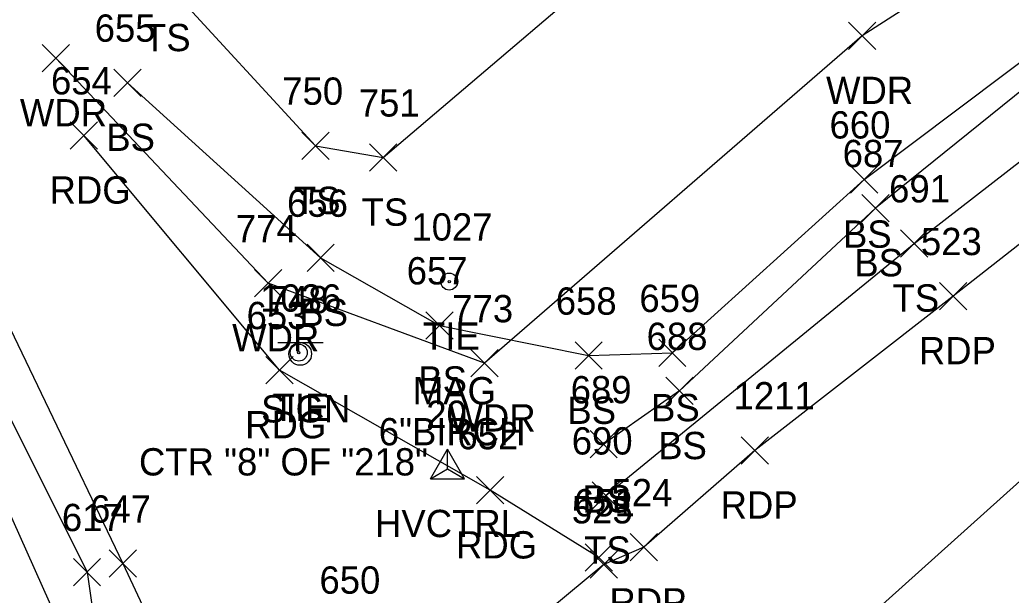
# Model space of a CAD drawing. Extents: x 1528286 to 1556263, y 492387 to 508952.
# Drawn here: x 1528468.6 to 1528541.2, y 492695.5 to 492737.7 of the extents above; entities that cross this region are included whole.
import ezdxf

# ---------------------------------------------------------------- set-up
doc = ezdxf.new("R2010")
doc.units = 0
for name, color, linetype in [('C_A', 7, 'Continuous'), ('C_C', 7, 'Continuous'), ('C_I', 7, 'Continuous'), ('CBP', 7, 'Continuous'), ('CPSM', 7, 'Continuous'), ('L_A', 7, 'Continuous'), ('L_I', 7, 'Continuous'), ('L_TIC', 7, 'Continuous'), ('LAWA', 7, 'Continuous'), ('LELB', 7, 'Continuous'), ('P_A', 7, 'Continuous'), ('P_I', 7, 'Continuous'), ('P_TIC', 7, 'Continuous'), ('PET', 7, 'Continuous'), ('PEU', 7, 'Continuous'), ('PRC', 7, 'Continuous'), ('S_A', 7, 'Continuous'), ('S_I', 7, 'Continuous'), ('SSGN', 7, 'Continuous')]:
    doc.layers.add(name, color=color, linetype=linetype)

msp = doc.modelspace()

# ---------------------------------------------------------------- linework, layer by layer
at = {"layer": 'CBP'}
for centre, radius in [((1528500.051, 492718.519), 0.625), ((1528500.051, 492718.519), 0.625), ((1528500.051, 492718.519), 0.0833), ((1528500.051, 492718.519), 0.0833), ((1528489.024, 492713.312), 0.625), ((1528489.024, 492713.312), 0.625), ((1528489.024, 492713.312), 0.0833), ((1528489.024, 492713.312), 0.0833)]:
    msp.add_circle(centre, radius, dxfattribs=at)
at = {"layer": 'CPSM'}
for p, q in [((1528498.671, 492704.074), (1528499.921, 492706.239)), ((1528498.671, 492704.074), (1528499.921, 492706.239)), ((1528501.171, 492704.074), (1528499.921, 492706.239)), ((1528499.921, 492704.795), (1528499.921, 492706.239)), ((1528501.171, 492704.074), (1528499.921, 492706.239)), ((1528499.921, 492704.795), (1528499.921, 492706.239)), ((1528498.671, 492704.074), (1528499.921, 492704.795)), ((1528498.671, 492704.074), (1528499.921, 492704.795)), ((1528499.921, 492704.795), (1528499.921, 492704.795)), ((1528499.921, 492704.795), (1528501.171, 492704.074)), ((1528499.921, 492704.795), (1528499.921, 492704.795)), ((1528499.921, 492704.795), (1528501.171, 492704.074)), ((1528498.671, 492704.074), (1528501.171, 492704.074)), ((1528498.671, 492704.074), (1528501.171, 492704.074))]:
    msp.add_line(p, q, dxfattribs=at)
at = {"layer": 'L_TIC'}
for points in [[(1528529.313, 492735.522), (1528531.313, 492737.522)], [(1528531.313, 492735.522), (1528529.313, 492737.522)], [(1528529.313, 492735.522), (1528531.313, 492737.522)], [(1528531.313, 492735.522), (1528529.313, 492737.522)], [(1528470.218, 492733.886), (1528472.218, 492735.886)], [(1528472.218, 492733.886), (1528470.218, 492735.886)], [(1528470.218, 492733.886), (1528472.218, 492735.886)], [(1528472.218, 492733.886), (1528470.218, 492735.886)], [(1528475.47, 492732.086), (1528477.47, 492734.086)], [(1528477.47, 492732.086), (1528475.47, 492734.086)], [(1528475.47, 492732.086), (1528477.47, 492734.086)], [(1528477.47, 492732.086), (1528475.47, 492734.086)], [(1528489.259, 492727.467), (1528491.259, 492729.467)], [(1528491.259, 492727.467), (1528489.259, 492729.467)], [(1528489.259, 492727.467), (1528491.259, 492729.467)], [(1528491.259, 492727.467), (1528489.259, 492729.467)], [(1528494.219, 492726.605), (1528496.219, 492728.605)], [(1528496.219, 492726.605), (1528494.219, 492728.605)], [(1528494.219, 492726.605), (1528496.219, 492728.605)], [(1528496.219, 492726.605), (1528494.219, 492728.605)], [(1528529.473, 492724.995), (1528531.473, 492726.995)], [(1528531.473, 492724.995), (1528529.473, 492726.995)], [(1528529.473, 492724.995), (1528531.473, 492726.995)], [(1528531.473, 492724.995), (1528529.473, 492726.995)], [(1528530.303, 492722.898), (1528532.303, 492724.898)], [(1528532.303, 492722.898), (1528530.303, 492724.898)], [(1528530.303, 492722.898), (1528532.303, 492724.898)], [(1528532.303, 492722.898), (1528530.303, 492724.898)], [(1528533.14, 492720.314), (1528535.14, 492722.314)], [(1528535.14, 492720.314), (1528533.14, 492722.314)], [(1528533.14, 492720.314), (1528535.14, 492722.314)], [(1528535.14, 492720.314), (1528533.14, 492722.314)], [(1528489.627, 492719.26), (1528491.627, 492721.26)], [(1528491.627, 492719.26), (1528489.627, 492721.26)], [(1528489.627, 492719.26), (1528491.627, 492721.26)], [(1528491.627, 492719.26), (1528489.627, 492721.26)], [(1528485.776, 492717.401), (1528487.776, 492719.401)], [(1528487.776, 492717.401), (1528485.776, 492719.401)], [(1528485.776, 492717.401), (1528487.776, 492719.401)], [(1528487.776, 492717.401), (1528485.776, 492719.401)], [(1528498.344, 492714.307), (1528500.344, 492716.307)], [(1528500.344, 492714.307), (1528498.344, 492716.307)], [(1528498.344, 492714.307), (1528500.344, 492716.307)], [(1528500.344, 492714.307), (1528498.344, 492716.307)], [(1528509.272, 492712.09), (1528511.272, 492714.09)], [(1528511.272, 492712.09), (1528509.272, 492714.09)], [(1528509.272, 492712.09), (1528511.272, 492714.09)], [(1528511.272, 492712.09), (1528509.272, 492714.09)], [(1528515.407, 492712.286), (1528517.407, 492714.286)], [(1528517.407, 492712.286), (1528515.407, 492714.286)], [(1528515.407, 492712.286), (1528517.407, 492714.286)], [(1528517.407, 492712.286), (1528515.407, 492714.286)], [(1528501.638, 492711.533), (1528503.638, 492713.533)], [(1528503.638, 492711.533), (1528501.638, 492713.533)], [(1528501.638, 492711.533), (1528503.638, 492713.533)], [(1528503.638, 492711.533), (1528501.638, 492713.533)], [(1528515.93, 492709.506), (1528517.93, 492711.506)], [(1528517.93, 492709.506), (1528515.93, 492711.506)], [(1528515.93, 492709.506), (1528517.93, 492711.506)], [(1528517.93, 492709.506), (1528515.93, 492711.506)], [(1528510.372, 492705.597), (1528512.372, 492707.597)], [(1528512.372, 492705.597), (1528510.372, 492707.597)], [(1528510.372, 492705.597), (1528512.372, 492707.597)], [(1528512.372, 492705.597), (1528510.372, 492707.597)], [(1528510.531, 492701.846), (1528512.531, 492703.846)], [(1528512.531, 492701.846), (1528510.531, 492703.846)], [(1528510.531, 492701.846), (1528512.531, 492703.846)], [(1528512.531, 492701.846), (1528510.531, 492703.846)], [(1528472.5, 492696.234), (1528474.5, 492698.234)], [(1528474.5, 492696.234), (1528472.5, 492698.234)], [(1528472.5, 492696.234), (1528474.5, 492698.234)], [(1528474.5, 492696.234), (1528472.5, 492698.234)]]:
    msp.add_lwpolyline(points, dxfattribs=at)
at = {"layer": 'LAWA'}
for points in [[(1528662.937, 492830.692), (1528634.182, 492809.012), (1528604.188, 492788.279), (1528566.961, 492760.007), (1528530.313, 492736.522), (1528502.638, 492712.533), (1528486.776, 492718.401), (1528471.218, 492734.886)], [(1528662.937, 492830.692), (1528634.182, 492809.012), (1528604.188, 492788.279), (1528566.961, 492760.007), (1528530.313, 492736.522), (1528502.638, 492712.533), (1528486.776, 492718.401), (1528471.218, 492734.886)], [(1528305.143, 492527.842), (1528342.933, 492565.336), (1528378.694, 492601.441), (1528416.012, 492639), (1528453.009, 492673.153), (1528472.803, 492690.435), (1528460.273, 492718.435)], [(1528305.143, 492527.842), (1528342.933, 492565.336), (1528378.694, 492601.441), (1528416.012, 492639), (1528453.009, 492673.153), (1528472.803, 492690.435), (1528460.273, 492718.435)]]:
    msp.add_lwpolyline(points, dxfattribs=at)
at = {"layer": 'LELB'}
for points in [[(1528511.531, 492702.846), (1528534.14, 492721.314), (1528572.642, 492751.164), (1528586.729, 492763.586), (1528600.497, 492766.346), (1528613.458, 492775.516), (1528652.2, 492802.526), (1528688.619, 492828.262), (1528710.289, 492843.118), (1528742.907, 492866.471), (1528778.713, 492891.266), (1528817.445, 492919.082), (1528857.746, 492946.937), (1528897.372, 492973.983), (1528940.286, 493003.739)], [(1528511.531, 492702.846), (1528534.14, 492721.314), (1528572.642, 492751.164), (1528586.729, 492763.586), (1528600.497, 492766.346), (1528613.458, 492775.516), (1528652.2, 492802.526), (1528688.619, 492828.262), (1528710.289, 492843.118), (1528742.907, 492866.471), (1528778.713, 492891.266), (1528817.445, 492919.082), (1528857.746, 492946.937), (1528897.372, 492973.983), (1528940.286, 493003.739)], [(1528479.267, 492740.393), (1528490.259, 492728.467), (1528495.219, 492727.605), (1528516.649, 492745.843), (1528531.015, 492756.158), (1528553.244, 492773.675), (1528563.708, 492774.042), (1528594.12, 492792.873), (1528616.34, 492816.289), (1528631.227, 492827.673), (1528655.587, 492852.622)], [(1528479.267, 492740.393), (1528490.259, 492728.467), (1528495.219, 492727.605), (1528516.649, 492745.843), (1528531.015, 492756.158), (1528553.244, 492773.675), (1528563.708, 492774.042), (1528594.12, 492792.873), (1528616.34, 492816.289), (1528631.227, 492827.673), (1528655.587, 492852.622)], [(1528476.47, 492733.086), (1528490.627, 492720.26), (1528499.344, 492715.307), (1528510.272, 492713.09), (1528516.407, 492713.286), (1528530.473, 492725.995), (1528568.475, 492754.562), (1528582.496, 492766.122), (1528590.696, 492769.852), (1528623.394, 492792.056), (1528660.048, 492816.01), (1528671.542, 492831.179), (1528678.095, 492847.611)], [(1528476.47, 492733.086), (1528490.627, 492720.26), (1528499.344, 492715.307), (1528510.272, 492713.09), (1528516.407, 492713.286), (1528530.473, 492725.995), (1528568.475, 492754.562), (1528582.496, 492766.122), (1528590.696, 492769.852), (1528623.394, 492792.056), (1528660.048, 492816.01), (1528671.542, 492831.179), (1528678.095, 492847.611)], [(1528685.936, 492838.575), (1528672.607, 492830.811), (1528666.617, 492820.24), (1528643.207, 492802.995), (1528614.904, 492783.769), (1528590.503, 492768.834), (1528580.049, 492763.591), (1528573.986, 492757.651), (1528555.822, 492743.679), (1528531.303, 492723.898), (1528516.93, 492710.506), (1528511.372, 492706.597)], [(1528685.936, 492838.575), (1528672.607, 492830.811), (1528666.617, 492820.24), (1528643.207, 492802.995), (1528614.904, 492783.769), (1528590.503, 492768.834), (1528580.049, 492763.591), (1528573.986, 492757.651), (1528555.822, 492743.679), (1528531.303, 492723.898), (1528516.93, 492710.506), (1528511.372, 492706.597)], [(1528463.974, 492716.24), (1528473.5, 492697.234), (1528475.042, 492686.518), (1528472.395, 492681.69), (1528457.302, 492666.687)], [(1528463.974, 492716.24), (1528473.5, 492697.234), (1528475.042, 492686.518), (1528472.395, 492681.69), (1528457.302, 492666.687)]]:
    msp.add_lwpolyline(points, dxfattribs=at)
at = {"layer": 'P_TIC'}
for points in [[(1528472.268, 492728.224), (1528474.268, 492730.224)], [(1528474.268, 492728.224), (1528472.268, 492730.224)], [(1528472.268, 492728.224), (1528474.268, 492730.224)], [(1528474.268, 492728.224), (1528472.268, 492730.224)], [(1528535.991, 492716.453), (1528537.991, 492718.453)], [(1528537.991, 492716.453), (1528535.991, 492718.453)], [(1528535.991, 492716.453), (1528537.991, 492718.453)], [(1528537.991, 492716.453), (1528535.991, 492718.453)], [(1528486.605, 492711.031), (1528488.605, 492713.031)], [(1528488.605, 492711.031), (1528486.605, 492713.031)], [(1528486.605, 492711.031), (1528488.605, 492713.031)], [(1528488.605, 492711.031), (1528486.605, 492713.031)], [(1528521.459, 492705.152), (1528523.459, 492707.152)], [(1528523.459, 492705.152), (1528521.459, 492707.152)], [(1528521.459, 492705.152), (1528523.459, 492707.152)], [(1528523.459, 492705.152), (1528521.459, 492707.152)], [(1528502.063, 492702.23), (1528504.063, 492704.23)], [(1528504.063, 492702.23), (1528502.063, 492704.23)], [(1528502.063, 492702.23), (1528504.063, 492704.23)], [(1528504.063, 492702.23), (1528502.063, 492704.23)], [(1528513.309, 492698.055), (1528515.309, 492700.055)], [(1528515.309, 492698.055), (1528513.309, 492700.055)], [(1528513.309, 492698.055), (1528515.309, 492700.055)], [(1528515.309, 492698.055), (1528513.309, 492700.055)], [(1528475.134, 492696.856), (1528477.134, 492698.856)], [(1528477.134, 492696.856), (1528475.134, 492698.856)], [(1528475.134, 492696.856), (1528477.134, 492698.856)], [(1528477.134, 492696.856), (1528475.134, 492698.856)], [(1528510.029, 492697.314), (1528512.029, 492699.314)], [(1528512.029, 492697.314), (1528510.029, 492699.314)], [(1528510.029, 492697.314), (1528512.029, 492699.314)], [(1528512.029, 492697.314), (1528510.029, 492699.314)], [(1528510.395, 492696.801), (1528512.395, 492698.801)], [(1528512.395, 492696.801), (1528510.395, 492698.801)], [(1528510.395, 492696.801), (1528512.395, 492698.801)], [(1528512.395, 492696.801), (1528510.395, 492698.801)]]:
    msp.add_lwpolyline(points, dxfattribs=at)
at = {"layer": 'PET'}
for points in [[(1528561.831, 492736.896), (1528536.991, 492717.453)], [(1528561.831, 492736.896), (1528536.991, 492717.453)], [(1528536.991, 492717.453), (1528522.459, 492706.152)], [(1528536.991, 492717.453), (1528522.459, 492706.152)], [(1528523.925, 492687.768), (1528545.219, 492706.888)], [(1528523.925, 492687.768), (1528545.219, 492706.888)], [(1528522.459, 492706.152), (1528514.309, 492699.055)], [(1528522.459, 492706.152), (1528514.309, 492699.055)], [(1528514.309, 492699.055), (1528511.395, 492697.801), (1528499.589, 492688), (1528484.561, 492674.516), (1528484.425, 492673.265)], [(1528514.309, 492699.055), (1528511.395, 492697.801), (1528499.589, 492688), (1528484.561, 492674.516), (1528484.425, 492673.265)]]:
    msp.add_lwpolyline(points, dxfattribs=at)
at = {"layer": 'PEU'}
for points in [[(1528511.029, 492698.314), (1528503.063, 492703.23), (1528487.605, 492712.031), (1528473.268, 492729.224)], [(1528511.029, 492698.314), (1528503.063, 492703.23), (1528487.605, 492712.031), (1528473.268, 492729.224)], [(1528464.703, 492721.592), (1528476.134, 492697.856), (1528480.12, 492689.363), (1528484.355, 492676.123)], [(1528464.703, 492721.592), (1528476.134, 492697.856), (1528480.12, 492689.363), (1528484.355, 492676.123)]]:
    msp.add_lwpolyline(points, dxfattribs=at)
at = {"layer": 'PRC'}
msp.add_lwpolyline([(1528545.219, 492706.888), (1528523.925, 492687.768)], dxfattribs=at)
msp.add_lwpolyline([(1528545.219, 492706.888), (1528523.925, 492687.768)], dxfattribs=at)
at = {"layer": 'SSGN'}
for p, q in [((1528487.48, 492714.049), (1528490.813, 492714.049)), ((1528487.48, 492714.049), (1528490.813, 492714.049)), ((1528489.127, 492713.215), (1528489.127, 492713.215)), ((1528489.127, 492713.215), (1528489.127, 492713.215))]:
    msp.add_line(p, q, dxfattribs=at)
msp.add_circle((1528489.127, 492713.215), 0.833, dxfattribs=at)
msp.add_circle((1528489.127, 492713.215), 0.833, dxfattribs=at)

# ---------------------------------------------------------------- texts
at = {"layer": 'C_A'}
for s, p in [('TIE', (1528498.13, 492713.519)), ('TIE', (1528498.13, 492713.519)), ('TIE', (1528487.103, 492708.312)), ('TIE', (1528487.103, 492708.312)), ('HVCTRL', (1528494.614, 492699.795)), ('HVCTRL', (1528494.614, 492699.795))]:
    msp.add_text(s, height=2, dxfattribs=at).set_placement(p)
at = {"layer": 'C_C'}
for s, p in [('MAG', (1528497.382, 492709.519)), ('MAG', (1528497.382, 492709.519)), ('6"BIRCH', (1528494.886, 492706.519)), ('6"BIRCH', (1528494.886, 492706.519)), ('CTR "8" OF "218"', (1528477.308, 492704.312)), ('CTR "8" OF "218"', (1528477.308, 492704.312))]:
    msp.add_text(s, height=2, dxfattribs=at).set_placement(p)
at = {"layer": 'C_I'}
for s, p in [('1027', (1528497.279, 492721.519)), ('1027', (1528497.279, 492721.519)), ('1026', (1528486.198, 492716.312)), ('1026', (1528486.198, 492716.312)), ('20', (1528498.37, 492707.795)), ('20', (1528498.37, 492707.795))]:
    msp.add_text(s, height=2, dxfattribs=at).set_placement(p)
at = {"layer": 'L_A'}
for s, p in [('TS', (1528477.677, 492735.393)), ('TS', (1528477.677, 492735.393)), ('WDR', (1528527.675, 492731.522)), ('WDR', (1528527.675, 492731.522)), ('WDR', (1528468.58, 492729.886)), ('WDR', (1528468.58, 492729.886)), ('BS', (1528474.911, 492728.086)), ('BS', (1528474.911, 492728.086)), ('TS', (1528488.669, 492723.467)), ('TS', (1528488.669, 492723.467)), ('TS', (1528493.628, 492722.605)), ('TS', (1528493.628, 492722.605)), ('BS', (1528528.914, 492720.995)), ('BS', (1528528.914, 492720.995)), ('BS', (1528529.744, 492718.898)), ('BS', (1528529.744, 492718.898)), ('TS', (1528532.549, 492716.314)), ('TS', (1528532.549, 492716.314)), ('BS', (1528489.068, 492715.26)), ('BS', (1528489.068, 492715.26)), ('WDR', (1528484.139, 492713.401)), ('WDR', (1528484.139, 492713.401)), ('BS', (1528497.785, 492710.307)), ('BS', (1528497.785, 492710.307)), ('BS', (1528508.713, 492708.09)), ('BS', (1528508.713, 492708.09)), ('BS', (1528514.848, 492708.286)), ('BS', (1528514.848, 492708.286)), ('WDR', (1528500, 492707.533)), ('WDR', (1528500, 492707.533)), ('BS', (1528515.371, 492705.506)), ('BS', (1528515.371, 492705.506)), ('BS', (1528509.813, 492701.597)), ('BS', (1528509.813, 492701.597)), ('TS', (1528509.94, 492697.846)), ('TS', (1528509.94, 492697.846))]:
    msp.add_text(s, height=2, dxfattribs=at).set_placement(p)
at = {"layer": 'L_I'}
for s, p in [('655', (1528474.06, 492736.086)), ('655', (1528474.06, 492736.086)), ('750', (1528487.811, 492731.467)), ('750', (1528487.811, 492731.467)), ('751', (1528493.423, 492730.605)), ('751', (1528493.423, 492730.605)), ('660', (1528527.93, 492728.995)), ('660', (1528527.93, 492728.995)), ('687', (1528528.893, 492726.898)), ('687', (1528528.893, 492726.898)), ('691', (1528532.297, 492724.314)), ('691', (1528532.297, 492724.314)), ('656', (1528488.163, 492723.26)), ('656', (1528488.163, 492723.26)), ('774', (1528484.414, 492721.401)), ('774', (1528484.414, 492721.401)), ('657', (1528496.934, 492718.307)), ('657', (1528496.934, 492718.307)), ('658', (1528507.863, 492716.09)), ('658', (1528507.863, 492716.09)), ('659', (1528513.99, 492716.286)), ('659', (1528513.99, 492716.286)), ('773', (1528500.276, 492715.533)), ('773', (1528500.276, 492715.533)), ('688', (1528514.521, 492713.506)), ('688', (1528514.521, 492713.506)), ('689', (1528508.955, 492709.597)), ('689', (1528508.955, 492709.597)), ('690', (1528509.034, 492705.846)), ('690', (1528509.034, 492705.846)), ('617', (1528471.657, 492700.234)), ('617', (1528471.657, 492700.234)), ('650', (1528490.54, 492695.653)), ('650', (1528490.54, 492695.653))]:
    msp.add_text(s, height=2, dxfattribs=at).set_placement(p)
at = {"layer": 'P_A'}
for s, p in [('RDG', (1528470.756, 492724.224)), ('RDG', (1528470.756, 492724.224)), ('RDP', (1528534.479, 492712.453)), ('RDP', (1528534.479, 492712.453)), ('RDG', (1528485.093, 492707.031)), ('RDG', (1528485.093, 492707.031)), ('RDP', (1528519.947, 492701.152)), ('RDP', (1528519.947, 492701.152)), ('RDG', (1528500.551, 492698.23)), ('RDG', (1528500.551, 492698.23)), ('RDP', (1528511.797, 492694.055)), ('RDP', (1528511.797, 492694.055))]:
    msp.add_text(s, height=2, dxfattribs=at).set_placement(p)
at = {"layer": 'P_I'}
for s, p in [('654', (1528470.858, 492732.224)), ('654', (1528470.858, 492732.224)), ('523', (1528534.629, 492720.453)), ('523', (1528534.629, 492720.453)), ('653', (1528485.195, 492715.031)), ('653', (1528485.195, 492715.031)), ('1211', (1528520.9, 492709.152)), ('1211', (1528520.9, 492709.152)), ('652', (1528500.653, 492706.23)), ('652', (1528500.653, 492706.23)), ('524', (1528511.947, 492702.055)), ('524', (1528511.947, 492702.055)), ('651', (1528509.187, 492701.314)), ('651', (1528509.187, 492701.314)), ('647', (1528473.724, 492700.856)), ('647', (1528473.724, 492700.856)), ('525', (1528509.033, 492700.801)), ('525', (1528509.033, 492700.801))]:
    msp.add_text(s, height=2, dxfattribs=at).set_placement(p)
at = {"layer": 'S_A'}
msp.add_text('SIGN', height=2, dxfattribs=at).set_placement((1528486.265, 492708.195))
msp.add_text('SIGN', height=2, dxfattribs=at).set_placement((1528486.265, 492708.195))
at = {"layer": 'S_I'}
msp.add_text('748', height=2, dxfattribs=at).set_placement((1528486.745, 492716.195))
msp.add_text('748', height=2, dxfattribs=at).set_placement((1528486.745, 492716.195))

doc.saveas('drawing.dxf')
